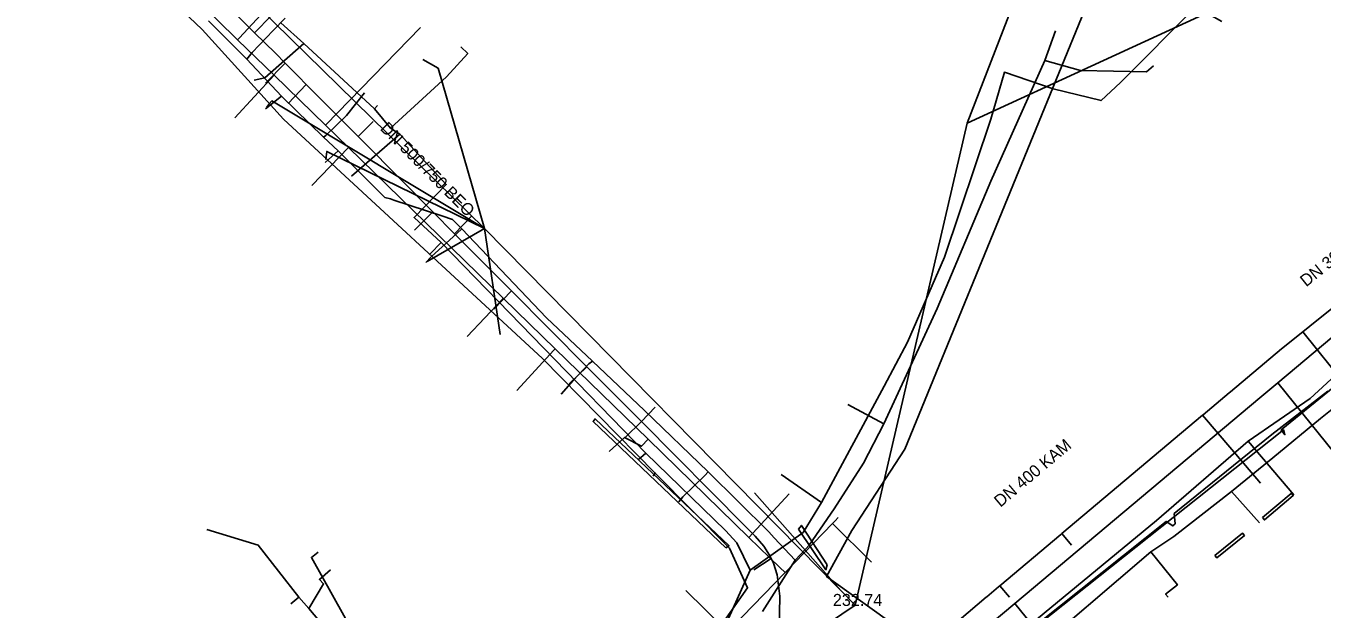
# Model space of a CAD drawing. Extents: x -598233 to -596890, y -1157848 to -1156431.
# Drawn here: x -597360.2 to -597274.3, y -1157423.2 to -1157384.6 of the extents above; entities that cross this region are included whole.
import ezdxf

# ---------------------------------------------------------------- set-up
doc = ezdxf.new("R2010")
doc.units = 0
for name, color, linetype in [('Vrstva 12', 7, 'Continuous'), ('Vrstva 13', 7, 'Continuous'), ('Vrstva 16', 7, 'Continuous'), ('Vrstva 3', 7, 'Continuous'), ('Vrstva 42', 7, 'Continuous'), ('Vrstva 51', 7, 'Continuous'), ('Vrstva 55', 7, 'Continuous'), ('Vrstva 9', 7, 'Continuous')]:
    doc.layers.add(name, color=color, linetype=linetype)

msp = doc.modelspace()

# ---------------------------------------------------------------- linework, layer by layer
at = {"layer": 'Vrstva 12'}
for points in [[(-597287.685, -1157388.314), (-597282.69, -1157383.31), (-597280.96, -1157384.28)], [(-597343.27, -1157384.36), (-597341.75, -1157385.74)], [(-597341.75, -1157385.74), (-597344.33, -1157388.01), (-597345.05, -1157388.16)], [(-597341.75, -1157385.74), (-597337.07, -1157390.06)], [(-597336.02, -1157391.35), (-597332.3, -1157387.95), (-597330.9, -1157386.39), (-597331.35, -1157385.95)], [(-597301.78, -1157405.52), (-597299.32, -1157399.89), (-597296.26, -1157390.74), (-597295.36, -1157387.64), (-597292.13, -1157388.74)], [(-597292.13, -1157388.74), (-597288.96, -1157389.51), (-597287.685, -1157388.314)], [(-597336.87, -1157389.84), (-597337.07, -1157390.06)], [(-597337.07, -1157390.06), (-597336.02, -1157391.35)], [(-597336.02, -1157391.35), (-597335.39, -1157391.74)], [(-597335.39, -1157391.74), (-597338.59, -1157394.53)], [(-597335.39, -1157391.74), (-597334.21, -1157393.04)], [(-597334.21, -1157393.04), (-597332.33, -1157395.07), (-597334.46, -1157397.27), (-597332.66, -1157398.92)], [(-597332.66, -1157398.92), (-597333.4, -1157399.67)], [(-597332.66, -1157398.92), (-597319.1, -1157412.89)], [(-597307.47, -1157416.16), (-597303.33, -1157408.44), (-597301.78, -1157405.52)], [(-597273.65, -1157409.96), (-597274.43, -1157410.59), (-597277.58, -1157413.19), (-597280.32, -1157415.43)], [(-597319.1, -1157412.89), (-597319.61, -1157413.33)], [(-597319.1, -1157412.89), (-597313.83, -1157418.02), (-597313.09, -1157418.83), (-597312.21, -1157420.64)], [(-597307.47, -1157416.16), (-597310.15, -1157414.3)], [(-597285.67, -1157419.43), (-597284.15, -1157418.4), (-597280.32, -1157415.43)], [(-597280.32, -1157415.43), (-597278.46, -1157417.5)], [(-597312.21, -1157420.64), (-597308.69, -1157418.15), (-597307.47, -1157416.16)], [(-597342.08, -1157422.43), (-597344.78, -1157418.98), (-597348.18, -1157417.94)], [(-597297.39, -1157429.16), (-597294.08, -1157426.63), (-597285.67, -1157419.43)], [(-597284.52, -1157422.43), (-597284.69, -1157422.24), (-597283.91, -1157421.61), (-597285.67, -1157419.43)], [(-597339.99, -1157420.61), (-597340.72, -1157421.25), (-597340.45, -1157421.55), (-597341.43, -1157423.19)], [(-597312.21, -1157420.64), (-597313.91, -1157424.49)], [(-597342.08, -1157422.43), (-597342.61, -1157422.88)], [(-597341.43, -1157423.19), (-597342.08, -1157422.43)], [(-597313.91, -1157424.49), (-597316.47, -1157421.98)], [(-597330.23, -1157439.26), (-597330.72, -1157437.28), (-597332.4, -1157433.7), (-597335.4, -1157430.29), (-597338.63, -1157426.52), (-597341.43, -1157423.19)]]:
    msp.add_lwpolyline(points, dxfattribs=at)
at = {"layer": 'Vrstva 13'}
for p, q in [((-597343.726, -1157387.833), (-597346.333, -1157390.664)), ((-597338.806, -1157392.627), (-597341.237, -1157395.153)), ((-597277.257, -1157408.213), (-597271.307, -1157415.616)), ((-597312.278, -1157418.47), (-597309.606, -1157415.578)), ((-597306.748, -1157417.557), (-597304.167, -1157420.102)), ((-597317.169, -1157428.318), (-597309.885, -1157420.796)), ((-597310.241, -1157420.454), (-597309.885, -1157420.796)), ((-597294.675, -1157422.841), (-597289.687, -1157428.991))]:
    msp.add_line(p, q, dxfattribs=at)
for points in [[(-597310.241, -1157420.454), (-597312.278, -1157418.47), (-597318.962, -1157411.959), (-597325.108, -1157405.972), (-597328.544, -1157402.625), (-597338.806, -1157392.627), (-597340.325, -1157391.147), (-597343.726, -1157387.833), (-597346.14, -1157385.482), (-597347.472, -1157384.184), (-597350.415, -1157381.316), (-597354.877, -1157376.969), (-597357.73, -1157374.188), (-597361.038, -1157370.965), (-597368.798, -1157363.405), (-597369.69, -1157362.488), (-597374.245, -1157358.099), (-597375.266, -1157357.105), (-597377.325, -1157355.099)], [(-597346.14, -1157385.482), (-597346.025, -1157385.357), (-597342.902, -1157381.981)], [(-597340.325, -1157391.147), (-597340.307, -1157391.129), (-597334.024, -1157384.675)], [(-597316.509, -1157428.953), (-597309.69, -1157435.445), (-597308.934, -1157434.811), (-597294.675, -1157422.841), (-597278.442, -1157409.209), (-597277.257, -1157408.213), (-597268.863, -1157401.168), (-597254.472, -1157389.086), (-597249.212, -1157384.67)], [(-597328.544, -1157402.625), (-597328.594, -1157402.679), (-597330.946, -1157405.153)], [(-597325.108, -1157405.972), (-597325.194, -1157406.063), (-597327.656, -1157408.729)], [(-597318.962, -1157411.959), (-597319.405, -1157412.426), (-597320.517, -1157411.841), (-597321.532, -1157412.771)], [(-597309.885, -1157420.796), (-597306.748, -1157417.557), (-597306.567, -1157417.37), (-597306.363, -1157417.16)]]:
    msp.add_lwpolyline(points, dxfattribs=at)
at = {"layer": 'Vrstva 16'}
for points in [[(-597310.97, -1157418.11), (-597314.98, -1157414.12), (-597319.2, -1157410.06), (-597322.64, -1157406.78), (-597325.68, -1157403.92), (-597331.29, -1157398.02), (-597331.921, -1157397.389), (-597332.61, -1157397.16), (-597335.79, -1157396.11), (-597336.02, -1157396.03), (-597336.4, -1157395.93), (-597339.49, -1157392.85), (-597340.46, -1157391.94), (-597343.24, -1157389.22), (-597345.53, -1157386.76), (-597348.07, -1157384.23)], [(-597345.53, -1157386.76), (-597345.17, -1157386.32), (-597343.78, -1157384.87), (-597343, -1157384.06)], [(-597309.21, -1157419.97), (-597308.52, -1157419.22), (-597308.3, -1157418.99), (-597306.63, -1157416.58), (-597304.7, -1157413.55), (-597303.34, -1157410.94), (-597299.81, -1157403.29), (-597296.26, -1157394.86), (-597292.68, -1157386.85), (-597291.99, -1157384.89)], [(-597223.92, -1157413.48), (-597225.62, -1157412.25), (-597233.72, -1157402.83), (-597237.12, -1157398.6), (-597240.63, -1157394.36), (-597244.69, -1157388.39), (-597246.72, -1157385.88), (-597259.5, -1157396.21), (-597263.44, -1157399.4), (-597271.78, -1157406.19), (-597275.11, -1157409.27), (-597279.22, -1157412.08), (-597285.28, -1157417.35), (-597297.14, -1157427.13), (-597300.56, -1157429.07), (-597304.45, -1157432.33), (-597304.87, -1157432.68), (-597310.66, -1157427.23)], [(-597292.68, -1157386.85), (-597290.33, -1157387.52), (-597285.95, -1157387.6), (-597285.5, -1157387.21)], [(-597340.46, -1157391.94), (-597340.31, -1157391.82), (-597338.93, -1157390.5), (-597337.74, -1157389)], [(-597343.24, -1157389.22), (-597344.29, -1157390.07)], [(-597339.49, -1157392.85), (-597340.35, -1157393.63)], [(-597331.29, -1157398.02), (-597331.6, -1157398.31), (-597333.32, -1157399.88), (-597333.67, -1157400.25)], [(-597322.64, -1157406.78), (-597322.88, -1157406.97), (-597323.91, -1157408.07), (-597324.72, -1157408.98)], [(-597303.34, -1157410.94), (-597305.73, -1157409.67)], [(-597279.22, -1157412.08), (-597276.19, -1157415.65)], [(-597316.92, -1157416.11), (-597316.65, -1157415.78), (-597315.21, -1157414.36), (-597314.98, -1157414.12)], [(-597309.21, -1157419.97), (-597310.62, -1157418.49), (-597310.97, -1157418.11)], [(-597309.21, -1157419.97), (-597311.38, -1157423.39)]]:
    msp.add_lwpolyline(points, dxfattribs=at)
at = {"layer": 'Vrstva 3'}
for points in [[(-597313.8, -1157419.17), (-597322.599, -1157410.776), (-597322.474, -1157410.615), (-597313.592, -1157419.024)], [(-597278.27, -1157417.16), (-597276.37, -1157415.55), (-597276.24, -1157415.7), (-597278.14, -1157417.31)], [(-597309.005, -1157417.922), (-597308.79, -1157417.672), (-597307.097, -1157420.284), (-597307.18, -1157420.618)], [(-597281.43, -1157419.67), (-597279.6, -1157418.18), (-597279.47, -1157418.34), (-597281.3, -1157419.82)]]:
    msp.add_lwpolyline(points, close=True, dxfattribs=at)
at = {"layer": 'Vrstva 42'}
msp.add_lwpolyline([(-597328.516, -1157451.786), (-597326.342, -1157450.125), (-597317.673, -1157443.91), (-597308.401, -1157436.79), (-597303.457, -1157432.614), (-597301.289, -1157431.125), (-597300.967, -1157431.396), (-597300.814, -1157431.272), (-597300.657, -1157431.145), (-597300.754, -1157430.604), (-597294.534, -1157425.309), (-597284.648, -1157417.411), (-597284.213, -1157417.708), (-597284.054, -1157417.569), (-597284.114, -1157416.887), (-597277.656, -1157411.658), (-597273.95, -1157408.774)], dxfattribs=at)
at = {"layer": 'Vrstva 51'}
for points in [[(-597305.25, -1157422.96), (-597297.82, -1157391.02), (-597282.69, -1157351.83)], [(-597355.53, -1157372.74), (-597329.8, -1157398)], [(-597297.82, -1157391.02), (-597279.78, -1157382.68)], [(-597329.8, -1157398), (-597332.86, -1157387.37), (-597333.87, -1157386.8)], [(-597329.8, -1157398), (-597343.87, -1157389.54), (-597344.23, -1157389.92)], [(-597329.8, -1157398), (-597340.24, -1157392.89), (-597340.3, -1157393.42)], [(-597329.8, -1157398), (-597333.59, -1157400.19)], [(-597329.8, -1157398), (-597328.76, -1157405.02)], [(-597329.8, -1157398), (-597306.202, -1157421.998), (-597305.25, -1157422.96)], [(-597306.202, -1157421.998), (-597311.91, -1157415.51)], [(-597330.13, -1157439.77), (-597341.25, -1157419.8), (-597340.8, -1157419.44)], [(-597305.25, -1157422.96), (-597330.13, -1157439.77)]]:
    msp.add_lwpolyline(points, dxfattribs=at)
at = {"layer": 'Vrstva 55'}
for points in [[(-597345.05, -1157454.85), (-597344.38, -1157454.64), (-597340.02, -1157460.65), (-597322.67, -1157446.47), (-597310.5, -1157437.5), (-597302.87, -1157431.81), (-597297.83, -1157427.73), (-597307.14, -1157421.07), (-597305.47, -1157418.015), (-597301.953, -1157412.621), (-597290.05, -1157383.55), (-597288.412, -1157376.549), (-597277.94, -1157351.2)], [(-597345.05, -1157454.85), (-597344.2, -1157454.54), (-597340.09, -1157460.44), (-597326.68, -1157449.71), (-597312.91, -1157439.52), (-597306.29, -1157434.51), (-597314.52, -1157424.86), (-597312.37, -1157421.82), (-597313.575, -1157419.177), (-597318.483, -1157414.201), (-597318.622, -1157414.381), (-597318.483, -1157414.201), (-597325.96, -1157406.62), (-597343.105, -1157390.75), (-597348.49, -1157384.81), (-597361.371, -1157372.543), (-597375.078, -1157358.836), (-597378, -1157358.16), (-597381.39, -1157359.59), (-597383.468, -1157361.845), (-597383.531, -1157361.997), (-597383.052, -1157362.213)], [(-597345.05, -1157454.85), (-597344.37, -1157454.64), (-597339.99, -1157460.69), (-597324.04, -1157447.73), (-597320.07, -1157445.38), (-597319.59, -1157446.67), (-597319.99, -1157445.38), (-597301.84, -1157431.2), (-597294.62, -1157425.6), (-597294.54, -1157426.01), (-597294.71, -1157425.52), (-597276.88, -1157411.34), (-597276.79, -1157411.66), (-597277.04, -1157411.34), (-597262.21, -1157399.26), (-597261.88, -1157399.67), (-597262.13, -1157399.26), (-597250.37, -1157389.62), (-597248.83, -1157389.86), (-597245.02, -1157386.21), (-597243.57, -1157383.54)]]:
    msp.add_lwpolyline(points, dxfattribs=at)
at = {"layer": 'Vrstva 9'}
for p, q in [((-597343.889, -1157383.877), (-597345.013, -1157385.024)), ((-597344.285, -1157388.362), (-597342.987, -1157387.043)), ((-597342.793, -1157389.701), (-597341.599, -1157388.441)), ((-597337.163, -1157390.894), (-597338.16, -1157391.904)), ((-597334.425, -1157398.104), (-597333.206, -1157396.892)), ((-597330.645, -1157397.187), (-597331.769, -1157398.339)), ((-597329.184, -1157403.349), (-597328.006, -1157402.128)), ((-597272.796, -1157408.339), (-597275.598, -1157404.84)), ((-597324.186, -1157408.288), (-597323.017, -1157407.152)), ((-597318.493, -1157409.846), (-597319.402, -1157410.792)), ((-597279.4, -1157413.697), (-597282.236, -1157410.37)), ((-597320.472, -1157411.851), (-597319.402, -1157410.792)), ((-597278.4, -1157414.87), (-597279.4, -1157413.697)), ((-597290.91, -1157418.98), (-597291.554, -1157418.215)), ((-597311.947, -1157420.619), (-597310.8, -1157419.867)), ((-597295.018, -1157422.438), (-597295.662, -1157421.673))]:
    msp.add_line(p, q, dxfattribs=at)
for points in [[(-597378.113, -1157352.194), (-597370.516, -1157359.73), (-597370.126, -1157360.116), (-597369.195, -1157361.039), (-597368.798, -1157361.433), (-597368.158, -1157362.067), (-597367.839, -1157362.384), (-597367.455, -1157362.765), (-597367.144, -1157363.074), (-597359.873, -1157370.286), (-597359.369, -1157370.785), (-597359.255, -1157370.898), (-597358.78, -1157371.37), (-597357.026, -1157373.109), (-597356.458, -1157373.672), (-597354.029, -1157376.081), (-597353.37, -1157376.736), (-597349.216, -1157380.856), (-597348.485, -1157381.581), (-597346.681, -1157383.37), (-597346, -1157384.045), (-597345.801, -1157384.243), (-597345.013, -1157385.024), (-597343.643, -1157386.383)], [(-597250.468, -1157384.709), (-597251.326, -1157385.396), (-597253.145, -1157386.853), (-597253.324, -1157386.996), (-597260.005, -1157392.349), (-597260.262, -1157392.555), (-597266.639, -1157397.663), (-597267.037, -1157397.982), (-597275.138, -1157404.472), (-597275.598, -1157404.84), (-597277.011, -1157405.972)], [(-597343.643, -1157386.383), (-597342.987, -1157387.043), (-597342.11, -1157387.927), (-597341.599, -1157388.441), (-597338.334, -1157391.729), (-597338.16, -1157391.904), (-597337.745, -1157392.322), (-597333.206, -1157396.892), (-597331.769, -1157398.339), (-597328.006, -1157402.128), (-597323.017, -1157407.152), (-597319.402, -1157410.792), (-597312.528, -1157417.714), (-597311.865, -1157418.377), (-597311.285, -1157419.04), (-597310.912, -1157419.642), (-597310.8, -1157419.867), (-597310.643, -1157420.181), (-597310.415, -1157420.948), (-597310.237, -1157422.374), (-597310.285, -1157424.634)], [(-597277.011, -1157405.972), (-597280.4, -1157408.825), (-597280.483, -1157408.895), (-597282.206, -1157410.345), (-597282.236, -1157410.37), (-597291.554, -1157418.215), (-597291.63, -1157418.279), (-597295.662, -1157421.673), (-597295.753, -1157421.75), (-597296.534, -1157422.408), (-597296.564, -1157422.433), (-597298.362, -1157423.947), (-597298.385, -1157423.966), (-597301.116, -1157426.266), (-597301.146, -1157426.291), (-597304.075, -1157428.757), (-597304.092, -1157428.771), (-597305.259, -1157429.754)]]:
    msp.add_lwpolyline(points, dxfattribs=at)

# ---------------------------------------------------------------- texts
at = {"layer": 'Vrstva 12'}
for s, rotation, p in [('DN 500/750 BEO', 314.80248, (-597336.752, -1157391.409)), ('DN 300 KAM', 38.67465, (-597275.382, -1157401.897)), ('DN 400 KAM', 40.10704, (-597295.629, -1157416.506))]:
    msp.add_text(s, height=0.8, rotation=rotation, dxfattribs=at).set_placement(p)
msp.add_text('232.74', height=0.8, dxfattribs=at).set_placement((-597306.722, -1157423.014))

doc.saveas('drawing.dxf')
